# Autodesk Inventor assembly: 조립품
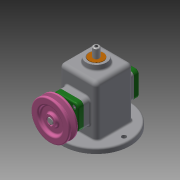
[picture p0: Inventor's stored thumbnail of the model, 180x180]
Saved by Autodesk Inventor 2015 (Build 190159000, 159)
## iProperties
Created: 2021-08
Part Number: 조립품
Document SubType Name: Assembly
Designer: 104589
Author: 104589
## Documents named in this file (16)
- C:\Users\104589\Desktop\710806V1021\조립품.iam
- C:\Users\104589\Desktop\710806V1021\V벨트풀리.ipt
- C:\Users\104589\Desktop\710806V1021\고정핀 1.2x8.ipt
- C:\Users\104589\Desktop\710806V1021\뒤커버.ipt
- C:\Users\104589\Desktop\710806V1021\링크.ipt
- C:\Users\104589\Desktop\710806V1021\멈춤나사 M3x8.ipt
- C:\Users\104589\Desktop\710806V1021\베어링 12x32x10.ipt
- C:\Users\104589\Desktop\710806V1021\본체.ipt
- C:\Users\104589\Desktop\710806V1021\볼트 M4.ipt
- C:\Users\104589\Desktop\710806V1021\부시.ipt
- C:\Users\104589\Desktop\710806V1021\슬라이드.ipt
- C:\Users\104589\Desktop\710806V1021\앞커버.ipt
- C:\Users\104589\Desktop\710806V1021\오일 실 12 25 7.ipt
- C:\Users\104589\Desktop\710806V1021\키 4x4x10.ipt
- C:\Users\104589\Desktop\710806V1021\편심축.ipt
- C:\Users\104589\Desktop\710806V1021\핀 5x18.ipt
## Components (3 placed, 3 different names)
1. V벨트풀리:1 — 플러쉬:2
2. 고정핀 1.2x8:1
3. 핀 5x18:1
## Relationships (1: Flush 1)
- 플러쉬:2 [Flush]: V벨트풀리:1
